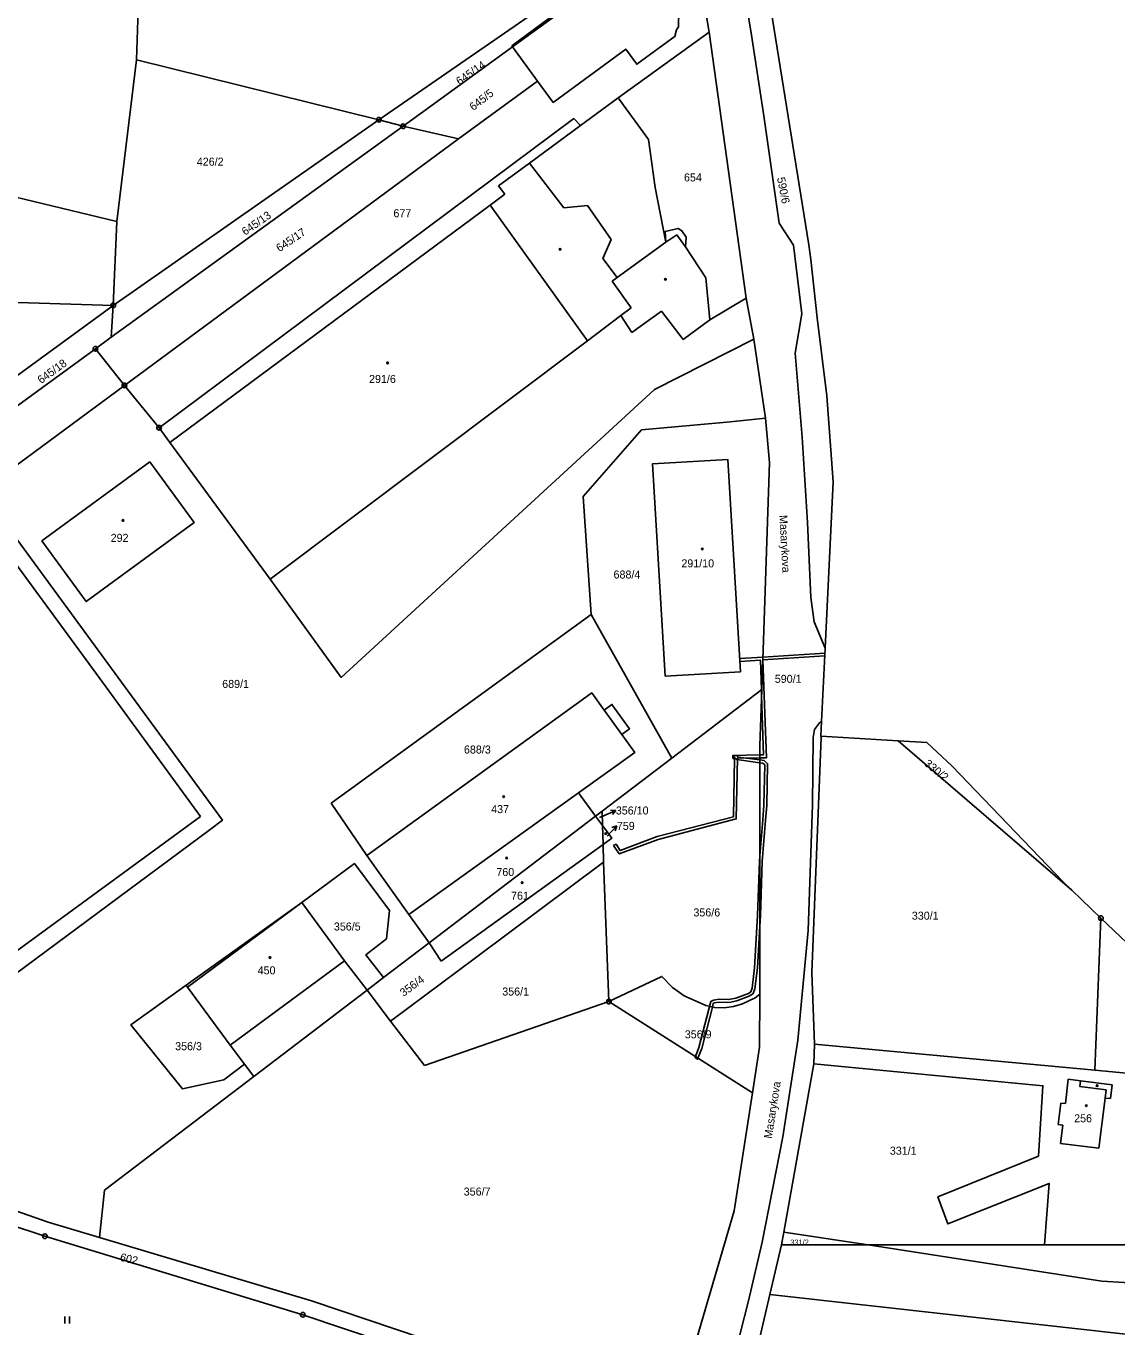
# Model space of a CAD drawing. Extents: x -758582 to -751794, y -998770 to -994350.
# Drawn here: x -756015.6 to -755783.8, y -994797.3 to -994520.9 of the extents above; entities that cross this region are included whole.
import ezdxf

# ---------------------------------------------------------------- set-up
doc = ezdxf.new("R2010")
doc.units = 0
for name, color, linetype in [('Hranice parcel', 7, 'Continuous'), ('Parcelní čísla', 7, 'Continuous'), ('Pop  PČ popisy', 7, 'Continuous'), ('Vnitřní kresba', 7, 'Continuous'), ('Věcná břemena k části', 7, 'Continuous'), ('Značky bodu BP', 7, 'Continuous'), ('Značky budov', 7, 'Continuous'), ('Značky kultur', 7, 'Continuous')]:
    doc.layers.add(name, color=color, linetype=linetype)

msp = doc.modelspace()

# ---------------------------------------------------------------- linework, layer by layer
at = {"layer": 'Hranice parcel'}
for p, q in [((-755940.65, -994540.79), (-755895.6, -994509.69)), ((-755872.98, -994507.74), (-755870.49, -994522.2)), ((-755912.41, -994525.09), (-755897.86, -994514.32)), ((-755991.83, -994517.46), (-755992.17, -994528.03)), ((-755870.49, -994522.2), (-755889.84, -994536.11)), ((-755870.49, -994522.2), (-755862.64, -994578.72)), ((-755912.26, -994525.3), (-755935.54, -994542.16)), ((-755912.26, -994525.3), (-755912.41, -994525.09)), ((-755912.26, -994525.3), (-755906.95, -994532.56)), ((-755992.17, -994528.03), (-755996.34, -994562.39)), ((-755940.65, -994540.79), (-755992.17, -994528.03)), ((-755923.78, -994544.85), (-755906.95, -994532.56)), ((-755906.95, -994532.56), (-755903.63, -994537.09)), ((-755883.35, -994545), (-755889.84, -994536.11)), ((-755997.58, -994586.99), (-755935.54, -994542.16)), ((-755997.13, -994580.23), (-755940.65, -994540.79)), ((-755935.54, -994542.16), (-755940.65, -994540.79)), ((-755935.54, -994542.16), (-755923.78, -994544.85)), ((-755923.78, -994544.85), (-755994.75, -994597.24)), ((-755881.98, -994555.15), (-755883.35, -994545)), ((-755996.34, -994562.39), (-755997.13, -994580.23)), ((-756080.29, -994577.63), (-755997.13, -994580.23)), ((-755861.01, -994587.39), (-755862.64, -994578.72)), ((-756026.54, -994601.71), (-755997.13, -994580.23)), ((-755997.13, -994580.23), (-755997.58, -994586.99)), ((-755997.58, -994586.99), (-756000.91, -994589.43)), ((-756000.91, -994589.43), (-756018.17, -994602.08)), ((-755994.75, -994597.24), (-756000.91, -994589.43)), ((-755861.01, -994587.39), (-755858.52, -994604.2)), ((-756027.92, -994621.72), (-755994.75, -994597.24)), ((-755994.75, -994597.24), (-755987.38, -994606.21)), ((-755844.13, -994617.73), (-755845.84, -994653.04)), ((-755950.8, -994685.95), (-755895.57, -994645.91)), ((-755895.57, -994645.91), (-755878.43, -994676.41)), ((-755846.59, -994668.65), (-755845.84, -994653.04)), ((-755859.3, -994661.84), (-755878.43, -994676.41)), ((-755847.04, -994668.89), (-755846.59, -994668.65)), ((-755846.74, -994671.72), (-755846.59, -994668.65)), ((-755844.33, -994671.86), (-755846.74, -994671.72)), ((-755846.74, -994671.72), (-755846.71, -994672.06)), ((-755830.35, -994672.72), (-755844.33, -994671.86)), ((-755793.42, -994704.48), (-755830.35, -994672.72)), ((-755824.21, -994673.09), (-755830.35, -994672.72)), ((-755818.82, -994678.11), (-755824.21, -994673.09)), ((-755878.43, -994676.41), (-755893.25, -994687.69)), ((-755795.28, -994702.7), (-755818.82, -994678.11)), ((-755934.29, -994709.61), (-755898.27, -994683.8)), ((-755898.27, -994683.8), (-755894.63, -994688.74)), ((-755943.24, -994697.12), (-755950.8, -994685.95)), ((-755929.99, -994715.67), (-755894.63, -994688.74)), ((-755894.63, -994688.74), (-755893.25, -994687.69)), ((-755894.63, -994688.74), (-755893.16, -994690.72)), ((-755893.25, -994687.69), (-755893.16, -994690.72)), ((-755893.16, -994690.72), (-755893.04, -994694.77)), ((-755893.04, -994694.77), (-755927.46, -994719.52)), ((-755892.93, -994698.54), (-755893.04, -994694.77)), ((-755943.24, -994697.12), (-755934.29, -994709.61)), ((-755891.8, -994728.13), (-755892.93, -994698.54)), ((-755793.42, -994704.48), (-755795.28, -994702.7)), ((-755787.25, -994710.38), (-755793.42, -994704.48)), ((-755957.06, -994707.11), (-755981.61, -994724.66)), ((-755929.99, -994715.67), (-755934.29, -994709.61)), ((-755788.56, -994742.71), (-755787.25, -994710.38)), ((-755775.14, -994721.98), (-755787.25, -994710.38)), ((-755929.99, -994715.67), (-755939.66, -994723.04)), ((-755927.46, -994719.52), (-755929.99, -994715.67)), ((-755939.66, -994723.04), (-755943.18, -994725.73)), ((-755967.24, -994744.05), (-755943.18, -994725.73)), ((-755943.18, -994725.73), (-755938.21, -994732.26)), ((-755930.98, -994741.74), (-755891.8, -994728.13)), ((-755861.28, -994747.52), (-755891.8, -994728.13)), ((-755860.72, -994727.35), (-755859.75, -994726.53)), ((-755938.21, -994732.26), (-755930.98, -994741.74)), ((-755848.13, -994737.19), (-755848.25, -994741.37)), ((-755788.56, -994742.71), (-755848.13, -994737.19)), ((-755969.2, -994741.46), (-755967.24, -994744.05)), ((-755854.65, -994777.1), (-755848.25, -994741.37)), ((-755855.14, -994779.83), (-755854.65, -994777.1)), ((-755854.65, -994777.1), (-755836.72, -994779.82)), ((-755857.6, -994790.33), (-755855.14, -994779.83)), ((-755855.14, -994779.83), (-755836.72, -994779.82)), ((-755799.24, -994779.81), (-755836.72, -994779.82)), ((-755860.46, -994802.54), (-755857.6, -994790.33)), ((-755685.31, -994809.56), (-755857.6, -994790.33))]:
    msp.add_line(p, q, dxfattribs=at)
for points in [[(-755845.84, -994653.04), (-755848.15, -994647.44), (-755848.87, -994642.3), (-755849.59, -994626.37), (-755850.7, -994608.2), (-755852.24, -994590.35), (-755850.76, -994582.03), (-755852.57, -994567.41), (-755855.61, -994562.75), (-755858.88, -994539.93), (-755861.49, -994522.8), (-755864.52, -994504.33), (-755867.42, -994488.56), (-755864.77, -994484.92)], [(-755874.42, -994498.13), (-755879.04, -994501.25), (-755912.26, -994525.3)], [(-755862.11, -994496.24), (-755857.72, -994514.93), (-755849.29, -994567.35), (-755848.88, -994570.49), (-755847.57, -994582.85), (-755845.5, -994599.47), (-755844.13, -994617.73)], [(-755903.63, -994537.09), (-755888.21, -994525.76), (-755885.87, -994529), (-755877.71, -994523.03), (-755877.68, -994522.76), (-755877.44, -994521.69), (-755876.99, -994521.02), (-755876.95, -994517.61), (-755877.01, -994517.22), (-755883.1, -994508.74), (-755883.44, -994507.59), (-755883.15, -994506.62), (-755882.02, -994505.08), (-755881.5, -994504.57), (-755879.28, -994504.31), (-755876.46, -994504.63), (-755874.87, -994505.36), (-755874.16, -994506.23)], [(-755889.84, -994536.11), (-755897.81, -994542.02), (-755899.21, -994540.55), (-755987.38, -994606.21)], [(-755996.34, -994562.39), (-756019.86, -994556.73), (-756052.75, -994545.97), (-756063.11, -994543.41)], [(-755862.64, -994578.72), (-755870.33, -994583.3), (-755871.19, -994574.35), (-755875.54, -994567.78), (-755875.39, -994565.7), (-755876.28, -994564.38), (-755877.1, -994563.87), (-755879.86, -994564.53), (-755879.7, -994566.79), (-755881.98, -994555.15)], [(-755987.38, -994606.21), (-755985.12, -994609.32), (-755963.75, -994638.41), (-755948.67, -994659.25), (-755882.07, -994598.06), (-755861.01, -994587.39)], [(-755884.84, -994606.64), (-755866.75, -994605.01), (-755863.95, -994604.77), (-755858.52, -994604.2)], [(-755858.52, -994604.2), (-755857.67, -994613.61), (-755859.3, -994661.84)], [(-755895.57, -994645.91), (-755897.24, -994620.8), (-755884.84, -994606.64)], [(-755989.33, -994613.49), (-756012.27, -994630.26), (-756002.86, -994643.14), (-755979.92, -994626.37), (-755989.33, -994613.49)], [(-755863.81, -994658.05), (-755879.82, -994659.02), (-755882.54, -994613.91), (-755866.54, -994612.94), (-755863.81, -994658.05)], [(-756074.68, -994743.51), (-756067.17, -994753.71), (-756037.59, -994731.95), (-756035.29, -994735.1), (-755976.55, -994691.57), (-755973.92, -994689.61), (-756021.09, -994625.18), (-756023.91, -994627.24), (-756027.92, -994621.72)], [(-755859.3, -994661.84), (-755859.71, -994673.81), (-755859.72, -994686.63), (-755859.75, -994726.53)], [(-755898.27, -994683.8), (-755886.29, -994675.21), (-755889.06, -994671.38), (-755887.4, -994670.18), (-755891.15, -994665), (-755892.79, -994666.19), (-755895.43, -994662.54), (-755943.24, -994697.12)], [(-755878.96, -994849), (-755870.67, -994823.33), (-755865.69, -994805.58), (-755862.15, -994791.68), (-755859.25, -994779.21), (-755854.8, -994756.88), (-755851.64, -994736.31), (-755849.48, -994713), (-755848.56, -994686.36), (-755848.37, -994672.01), (-755848.1, -994670.32), (-755847.04, -994668.89)], [(-755846.71, -994672.06), (-755848.64, -994721.98), (-755848.13, -994737.19)], [(-755893.16, -994690.72), (-755891.17, -994693.42), (-755893.04, -994694.77)], [(-755939.66, -994723.04), (-755943.47, -994718.21), (-755939.04, -994714.78), (-755938.42, -994708.8), (-755945.88, -994698.77), (-755957.06, -994707.11)], [(-755892.93, -994698.54), (-755920.13, -994718.8), (-755938.21, -994732.26)], [(-755943.18, -994725.73), (-755947.97, -994719.44), (-755957.06, -994707.11)], [(-755981.61, -994724.66), (-755993.36, -994733.06), (-755982.4, -994746.66), (-755973.58, -994744.72), (-755969.2, -994741.46)], [(-755981.61, -994724.66), (-755981.31, -994725.07), (-755972.29, -994737.37), (-755969.2, -994741.46)], [(-755891.8, -994728.13), (-755880.54, -994722.77), (-755878.27, -994725.11), (-755875.78, -994726.89), (-755871.22, -994728.94), (-755869.29, -994729.42), (-755867.31, -994729.47), (-755865.32, -994729.17), (-755863.39, -994728.64), (-755860.72, -994727.35)], [(-755859.75, -994726.53), (-755859.76, -994737.83), (-755861.28, -994747.52)], [(-755848.25, -994741.37), (-755799.57, -994746.01), (-755800.51, -994760.98), (-755821.86, -994769.63), (-755819.77, -994775.35), (-755798.25, -994766.76), (-755799.24, -994779.81)], [(-756000, -994778.26), (-755998.95, -994768.2), (-755967.24, -994744.05)], [(-755723.26, -994763.77), (-755776.73, -994760.65), (-755775.88, -994743.89), (-755788.56, -994742.71)], [(-755861.28, -994747.52), (-755865.2, -994772.6), (-755878.36, -994817.53)], [(-756000, -994778.26), (-756010.92, -994775), (-756033.91, -994766.97), (-756052.82, -994761.33), (-756074.89, -994755.28)], [(-756070.72, -994760.05), (-756053.87, -994764.58), (-756035.07, -994770.23), (-756011.64, -994777.98), (-755956.83, -994794.65), (-755879.3, -994820.73)], [(-755878.36, -994817.53), (-755955, -994791.7), (-756000, -994778.26)], [(-755836.72, -994779.82), (-755787.02, -994787.56), (-755734.87, -994790.65), (-755695.28, -994790.45)], [(-755799.24, -994779.81), (-755756.71, -994779.8), (-755702.04, -994779.39)]]:
    msp.add_lwpolyline(points, dxfattribs=at)
at = {"layer": 'Pop  PČ popisy'}
for p, q in [((-755893.78, -994689.03), (-755893.07, -994688.72)), ((-755893.07, -994688.72), (-755890.31, -994687.55)), ((-755890.31, -994687.55), (-755891.43, -994687.48)), ((-755890.31, -994687.55), (-755891.03, -994688.4)), ((-755892.19, -994692.96), (-755890.1, -994690.8)), ((-755890.1, -994690.8), (-755891.16, -994691.17)), ((-755890.1, -994690.8), (-755890.44, -994691.87))]:
    msp.add_line(p, q, dxfattribs=at)
at = {"layer": 'Vnitřní kresba'}
for p, q in [((-755908.65, -994550.01), (-755897.81, -994542.02)), ((-755915.22, -994554.85), (-755908.65, -994550.01)), ((-755901.38, -994559.52), (-755908.65, -994550.01)), ((-755916.99, -994558.9), (-755913.88, -994556.6)), ((-755913.88, -994556.6), (-755915.22, -994554.85)), ((-755985.12, -994609.32), (-755916.99, -994558.9)), ((-755916.99, -994558.9), (-755896.37, -994587.72)), ((-755901.38, -994559.52), (-755896.33, -994558.97)), ((-755896.33, -994558.97), (-755891.32, -994566.2)), ((-755891.32, -994566.2), (-755893.07, -994570.25)), ((-755879.7, -994566.79), (-755890.02, -994574.29)), ((-755879.7, -994566.79), (-755877.37, -994565.23)), ((-755875.54, -994567.78), (-755877.37, -994565.23)), ((-755890.02, -994574.29), (-755893.07, -994570.25)), ((-755891.12, -994575.09), (-755890.02, -994574.29)), ((-755887.08, -994580.72), (-755891.12, -994575.09)), ((-755889.22, -994582.4), (-755887.08, -994580.72)), ((-755886.89, -994585.97), (-755880.63, -994581.42)), ((-755880.63, -994581.42), (-755876.01, -994587.49)), ((-755889.22, -994582.4), (-755896.37, -994587.72)), ((-755889.22, -994582.4), (-755886.89, -994585.97)), ((-755876.01, -994587.49), (-755870.33, -994583.3)), ((-755896.37, -994587.72), (-755963.75, -994638.41)), ((-755999.99, -994659.49), (-756021.8, -994629.79)), ((-755999.99, -994659.49), (-755978.56, -994688.83)), ((-755892.79, -994666.19), (-755889.06, -994671.38)), ((-756037.59, -994731.95), (-755978.56, -994688.83)), ((-755957.06, -994707.11), (-755981.31, -994725.07)), ((-755947.97, -994719.44), (-755972.29, -994737.37)), ((-755794.17, -994744.62), (-755794.78, -994749.8)), ((-755791.57, -994744.95), (-755794.17, -994744.62)), ((-755791.72, -994746.17), (-755791.57, -994744.95)), ((-755786.13, -994746.85), (-755791.72, -994746.17)), ((-755784.86, -994745.8), (-755791.57, -994744.95)), ((-755786.35, -994748.62), (-755786.13, -994746.85)), ((-755785.22, -994748.75), (-755784.86, -994745.8)), ((-755795.77, -994749.68), (-755796.33, -994754.23)), ((-755794.78, -994749.8), (-755795.77, -994749.68)), ((-755787.68, -994759.29), (-755786.35, -994748.62)), ((-755786.35, -994748.62), (-755785.22, -994748.75)), ((-755796.33, -994754.23), (-755795.34, -994754.35)), ((-755795.34, -994754.35), (-755795.8, -994758.28)), ((-755795.8, -994758.28), (-755787.68, -994759.29))]:
    msp.add_line(p, q, dxfattribs=at)
at = {"layer": 'Věcná břemena k části'}
for points in [[(-755863.98, -994655.26), (-755863.94, -994655.87), (-755859.59, -994655.59), (-755859.38, -994661.9), (-755859.3, -994661.84), (-755859.09, -994655.56), (-755859.07, -994654.94)], [(-755858.32, -994676.31), (-755859.09, -994655.56), (-755859.34, -994663.13), (-755858.94, -994675.73), (-755859.71, -994675.74), (-755859.71, -994676.34)], [(-755845.92, -994654.69), (-755845.89, -994654.08), (-755859.07, -994654.94), (-755859.09, -994655.56)], [(-755881.32, -994693.67), (-755864.73, -994689.33), (-755864.47, -994676.45), (-755859.71, -994676.34), (-755859.71, -994675.74), (-755865.43, -994675.82), (-755865.43, -994676.48), (-755865.07, -994676.48), (-755865.33, -994688.87), (-755881.5, -994693.09), (-755889.4, -994696.03), (-755890.27, -994694.72), (-755890.81, -994694.98), (-755889.6, -994696.75)], [(-755864.62, -994676.73), (-755859.71, -994677.38), (-755859.71, -994676.79), (-755864.32, -994676.17), (-755864.63, -994675.84), (-755865.14, -994675.87), (-755865.1, -994676.47), (-755864.87, -994676.46)], [(-755858.66, -994677.86), (-755858.84, -994686.42), (-755859.08, -994689.55), (-755859.73, -994697.19), (-755859.74, -994712.13), (-755859.61, -994709.9), (-755859.22, -994698.34), (-755858.49, -994689.6), (-755858.25, -994686.45), (-755858.06, -994677.6), (-755858.82, -994676.91), (-755859.71, -994676.79), (-755859.71, -994677.38), (-755859.1, -994677.47)], [(-755864.79, -994727.39), (-755866.32, -994727.7), (-755868.38, -994727.63), (-755869.59, -994727.82), (-755870.13, -994728.13), (-755872.65, -994737.89), (-755873.39, -994739.83), (-755872.87, -994740.16), (-755872.07, -994738.07), (-755869.81, -994729.29), (-755869.61, -994728.53), (-755869.39, -994728.4), (-755868.34, -994728.23), (-755866.26, -994728.3), (-755864.63, -994727.97), (-755861.83, -994726.92), (-755861.14, -994726.43), (-755860.77, -994725.41), (-755860.24, -994720.98), (-755859.74, -994712.13), (-755859.73, -994697.19), (-755859.82, -994698.3), (-755860.21, -994709.87), (-755860.84, -994720.95), (-755861.37, -994725.29), (-755861.64, -994726.05), (-755862.11, -994726.38)], [(-755873.39, -994739.83), (-755873.47, -994740.04), (-755872.95, -994740.37), (-755872.87, -994740.16)]]:
    msp.add_lwpolyline(points, close=True, dxfattribs=at)
at = {"layer": 'Značky bodu BP'}
for centre, radius in [((-755940.65, -994540.79), 0.5), ((-755940.65, -994540.79), 0.0303), ((-755935.54, -994542.16), 0.5), ((-755935.54, -994542.16), 0.0303), ((-755997.13, -994580.23), 0.5), ((-755997.13, -994580.23), 0.0303), ((-756000.91, -994589.43), 0.5), ((-756000.91, -994589.43), 0.0303), ((-755994.75, -994597.24), 0.5), ((-755994.75, -994597.24), 0.0303), ((-755987.38, -994606.21), 0.5), ((-755987.38, -994606.21), 0.0303), ((-755787.25, -994710.38), 0.5), ((-755787.25, -994710.38), 0.0303), ((-755891.8, -994728.13), 0.5), ((-755891.8, -994728.13), 0.0303), ((-756011.64, -994777.98), 0.5), ((-756011.64, -994777.98), 0.0303), ((-755956.83, -994794.65), 0.5), ((-755956.83, -994794.65), 0.0303)]:
    msp.add_circle(centre, radius, dxfattribs=at)
at = {"layer": 'Značky budov'}
for centre in [(-755902.15, -994568.32), (-755879.77, -994574.7), (-755938.83, -994592.43), (-755995.03, -994625.92), (-755871.94, -994631.99), (-755914.14, -994684.6), (-755892.49, -994692.45), (-755913.51, -994697.61), (-755910.22, -994702.86), (-755963.8, -994718.77), (-755788.04, -994745.98), (-755790.35, -994750.25)]:
    msp.add_circle(centre, 0.175, dxfattribs=at)
at = {"layer": 'Značky kultur'}
for p, q in [((-756007.43, -994796.53), (-756007.43, -994795.03)), ((-756006.43, -994796.53), (-756006.43, -994795.03))]:
    msp.add_line(p, q, dxfattribs=at)

# ---------------------------------------------------------------- texts
at = {"layer": 'Parcelní čísla'}
for s, rotation, p in [('645/14', 35, (-755923.53, -994533.51)), ('645/5', 38, (-755920.6, -994538.96)), ('590/6', 281, (-755856.08, -994553.15)), ('645/13', 35, (-755969.08, -994565.45)), ('645/17', 34, (-755961.79, -994568.96)), ('645/18', 36, (-756012.44, -994596.97)), ('330/2', 321, (-755824.91, -994677.84)), ('356/4', 36, (-755935.43, -994727.15)), ('602', 346, (-755995.81, -994783.16))]:
    msp.add_text(s, height=1.7, rotation=rotation, dxfattribs=at).set_placement(p)
for s, height, p in [('426/2', 1.7, (-755979.36, -994550.54)), ('654', 1.7, (-755875.83, -994553.89)), ('677', 1.7, (-755937.58, -994561.5)), ('291/6', 1.7, (-755942.75, -994596.7)), ('292', 1.7, (-755997.66, -994630.46)), ('291/10', 1.7, (-755876.39, -994635.88)), ('688/4', 1.7, (-755890.8, -994638.25)), ('590/1', 1.7, (-755856.54, -994660.41)), ('689/1', 1.7, (-755973.96, -994661.49)), ('688/3', 1.7, (-755922.59, -994675.43)), ('437', 1.7, (-755916.81, -994688.09)), ('356/10', 1.7, (-755890.32, -994688.38)), ('759', 1.7, (-755890.1, -994691.66)), ('760', 1.7, (-755915.7, -994701.46)), ('761', 1.7, (-755912.58, -994706.48)), ('356/6', 1.7, (-755873.83, -994710.04)), ('356/5', 1.7, (-755950.23, -994713.03)), ('330/1', 1.7, (-755827.42, -994710.73)), ('450', 1.7, (-755966.43, -994722.34)), ('356/1', 1.7, (-755914.45, -994726.84)), ('356/9', 1.7, (-755875.67, -994735.93)), ('356/3', 1.7, (-755983.96, -994738.46)), ('256', 1.7, (-755792.93, -994753.77)), ('331/1', 1.7, (-755832.09, -994760.66)), ('356/7', 1.7, (-755922.64, -994769.34)), ('331/2', 1.14, (-755853.25, -994779.83))]:
    msp.add_text(s, height=height, dxfattribs=at).set_placement(p)
at = {"layer": 'Pop  PČ popisy'}
for rotation, p in [(273, (-755855.56, -994624.8)), (81, (-755857.19, -994757.33))]:
    msp.add_text('Masarykova', height=1.7, rotation=rotation, dxfattribs=at).set_placement(p)

doc.saveas('drawing.dxf')
